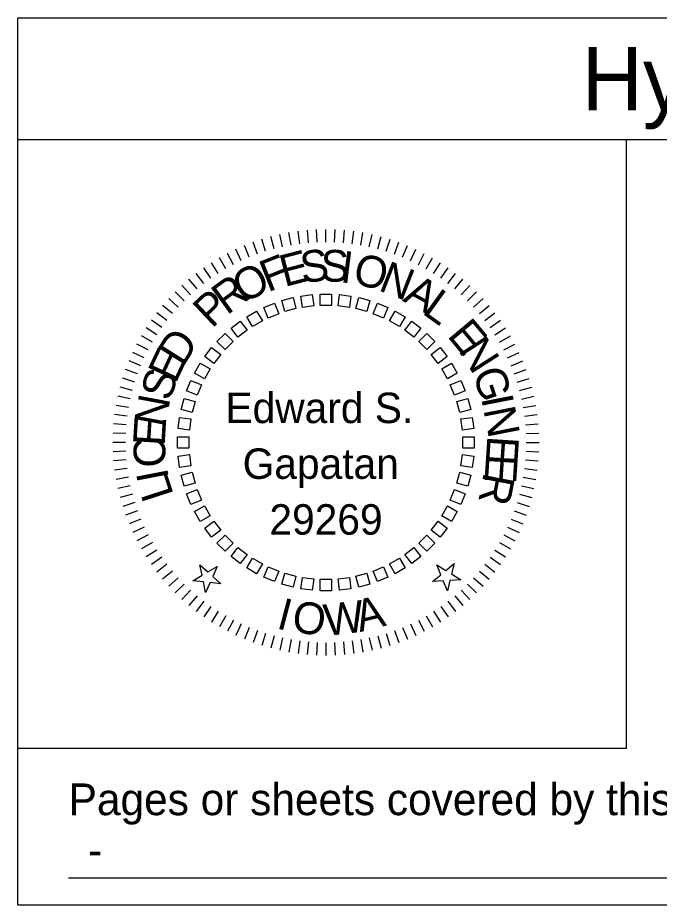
# Model space of a CAD drawing. Extents: x -0.84 to 4.97, y -1.01 to 2.42.
# Drawn here: x 4.3407 to 4.5514, y -0.6532 to -0.3615 of the extents above; entities that cross this region are included whole.
import ezdxf

# ---------------------------------------------------------------- set-up
doc = ezdxf.new("R2010")
doc.units = 0
for name, color, linetype in [('Level 1', 7, 'Continuous'), ('Level 2', 7, 'Continuous'), ('SheetGridMajor', 7, 'Continuous'), ('SheetGridMinor', 7, 'Continuous'), ('SheetText', 7, 'Continuous')]:
    doc.layers.add(name, color=color, linetype=linetype)

msp = doc.modelspace()

# ---------------------------------------------------------------- linework, layer by layer
at = {"layer": 'Level 1'}
for p, q in [((4.43333, -0.43576), (4.43279, -0.43163)), ((4.43619, -0.43545), (4.43583, -0.4313)), ((4.43906, -0.43526), (4.43887, -0.4311)), ((4.44193, -0.4352), (4.44193, -0.43103)), ((4.4448, -0.43526), (4.44498, -0.4311)), ((4.44766, -0.43545), (4.44803, -0.4313)), ((4.45052, -0.43576), (4.45106, -0.43163)), ((4.42213, -0.43825), (4.42088, -0.43427)), ((4.42489, -0.43744), (4.42381, -0.43342)), ((4.42768, -0.43676), (4.42678, -0.43269)), ((4.43049, -0.4362), (4.42977, -0.4321)), ((4.45336, -0.4362), (4.45408, -0.4321)), ((4.45618, -0.43676), (4.45708, -0.43269)), ((4.45897, -0.43744), (4.46004, -0.43342)), ((4.46172, -0.43825), (4.46298, -0.43427)), ((4.41673, -0.44021), (4.41514, -0.43636)), ((4.41941, -0.43917), (4.41799, -0.43526)), ((4.46444, -0.43917), (4.46587, -0.43526)), ((4.46712, -0.44021), (4.46871, -0.43636)), ((4.40901, -0.44402), (4.40693, -0.44041)), ((4.41153, -0.44264), (4.4096, -0.43894)), ((4.4141, -0.44137), (4.41234, -0.43759)), ((4.46975, -0.44137), (4.47151, -0.43759)), ((4.47232, -0.44264), (4.47425, -0.43894)), ((4.47484, -0.44402), (4.47693, -0.44041)), ((4.40655, -0.44551), (4.40432, -0.442)), ((4.4773, -0.44551), (4.47954, -0.442)), ((4.40185, -0.4488), (4.39931, -0.4455)), ((4.40417, -0.44711), (4.40178, -0.44369)), ((4.47969, -0.44711), (4.48208, -0.44369)), ((4.482, -0.44881), (4.48454, -0.4455)), ((4.39961, -0.4506), (4.39693, -0.44741)), ((4.48424, -0.4506), (4.48692, -0.44741)), ((4.39538, -0.45448), (4.39243, -0.45154)), ((4.39745, -0.4525), (4.39464, -0.44942)), ((4.4864, -0.4525), (4.48922, -0.44943)), ((4.48848, -0.45448), (4.49142, -0.45154)), ((4.39339, -0.45656), (4.39032, -0.45374)), ((4.49046, -0.45656), (4.49354, -0.45374)), ((4.3915, -0.45872), (4.3883, -0.45604)), ((4.49236, -0.45872), (4.49555, -0.45604)), ((4.3897, -0.46096), (4.38639, -0.45842)), ((4.49416, -0.46096), (4.49746, -0.45842)), ((4.3864, -0.46566), (4.38289, -0.46342)), ((4.388, -0.46327), (4.38459, -0.46088)), ((4.49585, -0.46327), (4.49927, -0.46088)), ((4.49745, -0.46566), (4.50096, -0.46342)), ((4.38491, -0.46812), (4.38131, -0.46603)), ((4.49894, -0.46812), (4.50255, -0.46603)), ((4.38353, -0.47064), (4.37984, -0.46871)), ((4.50032, -0.47064), (4.50402, -0.46871)), ((4.38226, -0.47321), (4.37849, -0.47145)), ((4.50159, -0.47321), (4.50537, -0.47145)), ((4.3811, -0.47584), (4.37726, -0.47425)), ((4.50275, -0.47584), (4.5066, -0.47425)), ((4.38006, -0.47852), (4.37615, -0.47709)), ((4.50379, -0.47852), (4.5077, -0.47709)), ((4.37914, -0.48124), (4.37517, -0.47998)), ((4.50471, -0.48124), (4.50869, -0.47999)), ((4.37834, -0.48399), (4.37431, -0.48292)), ((4.50552, -0.484), (4.50954, -0.48292)), ((4.37765, -0.48678), (4.37359, -0.48588)), ((4.5062, -0.48679), (4.51027, -0.48588)), ((4.37709, -0.4896), (4.37299, -0.48888)), ((4.50676, -0.4896), (4.51086, -0.48888)), ((4.37666, -0.49244), (4.37253, -0.4919)), ((4.5072, -0.49244), (4.51133, -0.4919)), ((4.37634, -0.4953), (4.37219, -0.49493)), ((4.50751, -0.4953), (4.51166, -0.49493)), ((4.37616, -0.49816), (4.37199, -0.49798)), ((4.5077, -0.49816), (4.51186, -0.49798)), ((4.37609, -0.50103), (4.37193, -0.50103)), ((4.50776, -0.50103), (4.51193, -0.50103)), ((4.37616, -0.5039), (4.37199, -0.50409)), ((4.5077, -0.50391), (4.51186, -0.50409)), ((4.37634, -0.50677), (4.37219, -0.50713)), ((4.50751, -0.50677), (4.51166, -0.50714)), ((4.37666, -0.50963), (4.37253, -0.51017)), ((4.5072, -0.50963), (4.51133, -0.51017)), ((4.37709, -0.51247), (4.37299, -0.51319)), ((4.50676, -0.51247), (4.51086, -0.51319)), ((4.37765, -0.51528), (4.37359, -0.51618)), ((4.5062, -0.51528), (4.51027, -0.51618)), ((4.37834, -0.51807), (4.37431, -0.51915)), ((4.50552, -0.51807), (4.50954, -0.51915)), ((4.37914, -0.52083), (4.37517, -0.52208)), ((4.50471, -0.52083), (4.50869, -0.52208)), ((4.38006, -0.52355), (4.37615, -0.52497)), ((4.50379, -0.52355), (4.5077, -0.52498)), ((4.3811, -0.52623), (4.37725, -0.52782)), ((4.50275, -0.52623), (4.5066, -0.52782)), ((4.38226, -0.52886), (4.37848, -0.53062)), ((4.50159, -0.52886), (4.50537, -0.53062)), ((4.38353, -0.53143), (4.37984, -0.53336)), ((4.50032, -0.53143), (4.50402, -0.53336)), ((4.38491, -0.53395), (4.3813, -0.53603)), ((4.3864, -0.53641), (4.38289, -0.53864)), ((4.49745, -0.53641), (4.50096, -0.53864)), ((4.49894, -0.53395), (4.50255, -0.53603)), ((4.388, -0.53879), (4.38459, -0.54118)), ((4.49585, -0.53879), (4.49927, -0.54118)), ((4.3897, -0.54111), (4.38639, -0.54365)), ((4.49415, -0.54111), (4.49746, -0.54365)), ((4.39149, -0.54335), (4.3883, -0.54603)), ((4.49236, -0.54335), (4.49555, -0.54603)), ((4.39339, -0.54551), (4.39032, -0.54832)), ((4.39537, -0.54758), (4.39243, -0.55053)), ((4.48848, -0.54759), (4.49142, -0.55053)), ((4.49046, -0.54551), (4.49353, -0.54833)), ((4.39745, -0.54957), (4.39463, -0.55264)), ((4.4864, -0.54957), (4.48922, -0.55264)), ((4.39961, -0.55146), (4.39693, -0.55466)), ((4.40185, -0.55326), (4.39931, -0.55657)), ((4.482, -0.55326), (4.48454, -0.55657)), ((4.48424, -0.55147), (4.48692, -0.55466)), ((4.40417, -0.55496), (4.40178, -0.55837)), ((4.40655, -0.55656), (4.40432, -0.56007)), ((4.4773, -0.55656), (4.47954, -0.56007)), ((4.47969, -0.55496), (4.48208, -0.55837)), ((4.40901, -0.55805), (4.40693, -0.56165)), ((4.41153, -0.55943), (4.4096, -0.56312)), ((4.47232, -0.55943), (4.47425, -0.56312)), ((4.47484, -0.55805), (4.47693, -0.56166)), ((4.4141, -0.5607), (4.41234, -0.56447)), ((4.41673, -0.56186), (4.41514, -0.5657)), ((4.41941, -0.5629), (4.41798, -0.56681)), ((4.46444, -0.5629), (4.46587, -0.56681)), ((4.46712, -0.56186), (4.46871, -0.56571)), ((4.46975, -0.5607), (4.47151, -0.56448)), ((4.42213, -0.56382), (4.42088, -0.56779)), ((4.42489, -0.56462), (4.42381, -0.56865)), ((4.42768, -0.56531), (4.42678, -0.56937)), ((4.45617, -0.56531), (4.45708, -0.56937)), ((4.45896, -0.56462), (4.46004, -0.56865)), ((4.46172, -0.56382), (4.46297, -0.56779)), ((4.43049, -0.56587), (4.42977, -0.56997)), ((4.43333, -0.5663), (4.43279, -0.57043)), ((4.43619, -0.56662), (4.43582, -0.57077)), ((4.43905, -0.5668), (4.43887, -0.57097)), ((4.44193, -0.56687), (4.44193, -0.57103)), ((4.4448, -0.5668), (4.44498, -0.57097)), ((4.44766, -0.56662), (4.44803, -0.57077)), ((4.45052, -0.5663), (4.45106, -0.57043)), ((4.45336, -0.56587), (4.45408, -0.56997))]:
    msp.add_line(p, q, dxfattribs=at)
for points in [[(4.43209, -0.45708), (4.42847, -0.45805), (4.4275, -0.45443), (4.43112, -0.45346)], [(4.43791, -0.45617), (4.43419, -0.45666), (4.4337, -0.45295), (4.43742, -0.45246)], [(4.4438, -0.45603), (4.44005, -0.45603), (4.44005, -0.45228), (4.4438, -0.45228)], [(4.44966, -0.45666), (4.44594, -0.45617), (4.44643, -0.45246), (4.45015, -0.45295)], [(4.45538, -0.45805), (4.45176, -0.45708), (4.45273, -0.45346), (4.45635, -0.45443)], [(4.42105, -0.46112), (4.4178, -0.463), (4.41593, -0.45975), (4.41917, -0.45788)], [(4.42644, -0.45874), (4.42297, -0.46018), (4.42154, -0.45671), (4.425, -0.45528)], [(4.46088, -0.46018), (4.45741, -0.45874), (4.45885, -0.45528), (4.46231, -0.45671)], [(4.46605, -0.463), (4.4628, -0.46113), (4.46468, -0.45788), (4.46792, -0.45975)], [(4.41602, -0.46419), (4.41304, -0.46647), (4.41076, -0.4635), (4.41374, -0.46122)], [(4.47081, -0.46647), (4.46783, -0.46419), (4.47012, -0.46122), (4.47309, -0.4635)], [(4.41143, -0.46789), (4.40878, -0.47054), (4.40613, -0.46789), (4.40878, -0.46524)], [(4.47507, -0.47054), (4.47242, -0.46789), (4.47507, -0.46524), (4.47772, -0.46789)], [(4.40737, -0.47215), (4.40508, -0.47513), (4.40211, -0.47284), (4.40439, -0.46987)], [(4.47877, -0.47513), (4.47649, -0.47215), (4.47946, -0.46987), (4.48174, -0.47284)], [(4.40389, -0.47691), (4.40202, -0.48016), (4.39877, -0.47828), (4.40064, -0.47504)], [(4.48184, -0.48016), (4.47996, -0.47691), (4.48321, -0.47503), (4.48508, -0.47828)], [(4.40107, -0.48208), (4.39963, -0.48555), (4.39617, -0.48411), (4.3976, -0.48065)], [(4.48422, -0.48555), (4.48278, -0.48208), (4.48625, -0.48065), (4.48768, -0.48411)], [(4.39894, -0.48758), (4.39797, -0.4912), (4.39435, -0.49023), (4.39532, -0.48661)], [(4.48588, -0.4912), (4.48491, -0.48758), (4.48853, -0.4866), (4.4895, -0.49023)], [(4.39756, -0.4933), (4.39707, -0.49702), (4.39335, -0.49653), (4.39384, -0.49281)], [(4.48679, -0.49702), (4.4863, -0.4933), (4.49001, -0.49281), (4.4905, -0.49653)], [(4.39693, -0.49916), (4.39693, -0.50291), (4.39318, -0.50291), (4.39318, -0.49916)], [(4.48693, -0.50291), (4.48693, -0.49916), (4.49068, -0.49916), (4.49068, -0.50291)], [(4.39707, -0.50505), (4.39756, -0.50877), (4.39384, -0.50926), (4.39335, -0.50554)], [(4.4863, -0.50877), (4.48679, -0.50505), (4.4905, -0.50554), (4.49001, -0.50926)], [(4.39797, -0.51087), (4.39895, -0.51449), (4.39532, -0.51546), (4.39435, -0.51184)], [(4.48491, -0.51449), (4.48588, -0.51087), (4.4895, -0.51184), (4.48853, -0.51546)], [(4.39963, -0.51652), (4.40107, -0.51999), (4.3976, -0.52142), (4.39617, -0.51796)], [(4.48278, -0.51999), (4.48422, -0.51652), (4.48768, -0.51796), (4.48625, -0.52142)], [(4.40202, -0.52191), (4.40389, -0.52516), (4.40064, -0.52703), (4.39877, -0.52379)], [(4.47996, -0.52516), (4.48183, -0.52191), (4.48508, -0.52379), (4.48321, -0.52703)], [(4.40508, -0.52694), (4.40737, -0.52992), (4.40439, -0.5322), (4.40211, -0.52922)], [(4.47649, -0.52992), (4.47877, -0.52694), (4.48174, -0.52922), (4.47946, -0.5322)], [(4.40878, -0.53153), (4.41143, -0.53418), (4.40878, -0.53683), (4.40613, -0.53418)], [(4.47242, -0.53418), (4.47507, -0.53153), (4.47772, -0.53418), (4.47507, -0.53683)], [(4.41304, -0.53559), (4.41602, -0.53788), (4.41374, -0.54085), (4.41076, -0.53857)], [(4.46783, -0.53788), (4.47081, -0.53559), (4.47309, -0.53857), (4.47012, -0.54085)], [(4.4178, -0.53907), (4.42105, -0.54094), (4.41917, -0.54419), (4.41593, -0.54232)], [(4.4628, -0.54094), (4.46605, -0.53907), (4.46793, -0.54232), (4.46468, -0.54419)], [(4.40049, -0.54126), (4.40313, -0.54363), (4.4062, -0.54186), (4.40476, -0.5451), (4.40739, -0.54747), (4.40386, -0.5471), (4.40242, -0.55034), (4.40169, -0.54687), (4.39816, -0.5465), (4.40123, -0.54473)], [(4.42297, -0.54189), (4.42644, -0.54333), (4.425, -0.54679), (4.42154, -0.54536)], [(4.45741, -0.54333), (4.46088, -0.54189), (4.46231, -0.54536), (4.45885, -0.54679)], [(4.47834, -0.54124), (4.48135, -0.54312), (4.48407, -0.54085), (4.48321, -0.54429), (4.48621, -0.54616), (4.48268, -0.54641), (4.48182, -0.54985), (4.48049, -0.54656), (4.47695, -0.54681), (4.47967, -0.54453)], [(4.42847, -0.54402), (4.43209, -0.54499), (4.43112, -0.54861), (4.4275, -0.54764)], [(4.43419, -0.5454), (4.43791, -0.54589), (4.43742, -0.54961), (4.4337, -0.54912)], [(4.44594, -0.54589), (4.44966, -0.5454), (4.45015, -0.54912), (4.44643, -0.54961)], [(4.45176, -0.54499), (4.45538, -0.54401), (4.45636, -0.54764), (4.45273, -0.54861)], [(4.44005, -0.54603), (4.4438, -0.54603), (4.4438, -0.54978), (4.44005, -0.54978)]]:
    msp.add_lwpolyline(points, close=True, dxfattribs=at)
at = {"layer": 'SheetGridMajor'}
for p, q in [((4.3407, -0.40149), (4.9657, -0.40149)), ((4.5407, -0.60149), (4.5407, -0.40149)), ((4.3407, -0.60149), (4.5407, -0.60149))]:
    msp.add_line(p, q, dxfattribs=at)
msp.add_lwpolyline([(4.3407, -0.36149), (4.9657, -0.36149), (4.9657, -0.65315), (4.3407, -0.65315)], close=True, dxfattribs=at)
at = {"layer": 'SheetGridMinor'}
msp.add_line((4.35742, -0.64418), (4.94904, -0.64418), dxfattribs=at)

# ---------------------------------------------------------------- texts
at = {"layer": 'Level 1'}
for s, rotation, p in [('S', 7.3911, (4.43418, -0.44878)), ('F', 21.7736, (4.42287, -0.45178)), ('E', 14.5823, (4.42833, -0.45)), ('S', 0.1998, (4.44027, -0.44823)), ('I', 353.0085, (4.44638, -0.44837)), ('O', 345.8172, (4.45032, -0.44868)), ('O', 28.9649, (4.41494, -0.45561)), ('N', 338.6259, (4.45885, -0.45094)), ('R', 36.1562, (4.4094, -0.45939)), ('A', 331.4346, (4.46687, -0.45448)), ('P', 43.3475, (4.40444, -0.46379)), ('L', 324.2434, (4.4732, -0.45848)), ('E', 309.8608, (4.48152, -0.46605)), ('D', 57.7301, (4.39498, -0.47647)), ('N', 302.6695, (4.48524, -0.47074)), ('E', 64.9213, (4.39255, -0.48195)), ('S', 72.1126, (4.39071, -0.48779)), ('G', 288.2869, (4.48999, -0.47818)), ('N', 79.3039, (4.38905, -0.49642)), ('I', 281.0956, (4.49287, -0.48639)), ('N', 281.0956, (4.49363, -0.49025)), ('E', 86.4952, (4.38893, -0.50242)), ('C', 93.6865, (4.38952, -0.50899)), ('E', 266.2773, (4.495, -0.49873)), ('E', 266.2773, (4.49461, -0.5047)), ('I', 100.8778, (4.39042, -0.51284)), ('L', 108.069, (4.39199, -0.51825)), ('R', 259.086, (4.49386, -0.51063)), ('I', 345.2906, (4.42536, -0.56206)), ('O', 352.4819, (4.43046, -0.5633)), ('W', 6.8645, (4.44187, -0.56473)), ('A', 14.0557, (4.45304, -0.56343))]:
    msp.add_text(s, height=0.01042, rotation=rotation, dxfattribs=at).set_placement(p)
at = {"layer": 'Level 2'}
for s, p in [('Edward S.', (4.40893, -0.4947)), ('Gapatan', (4.41458, -0.51303)), ('29269', (4.42337, -0.53136))]:
    msp.add_text(s, height=0.01, dxfattribs=at).set_placement(p)
at = {"layer": 'SheetText'}
for s, height, p in [('Hydraulic Design', 0.0208333, (4.52596, -0.3919)), ('Pages or sheets covered by this seal:', 0.0104167, (4.35742, -0.62355)), ('-', 0.0104, (4.36379, -0.64015))]:
    msp.add_text(s, height=height, dxfattribs=at).set_placement(p)

doc.saveas('drawing.dxf')
